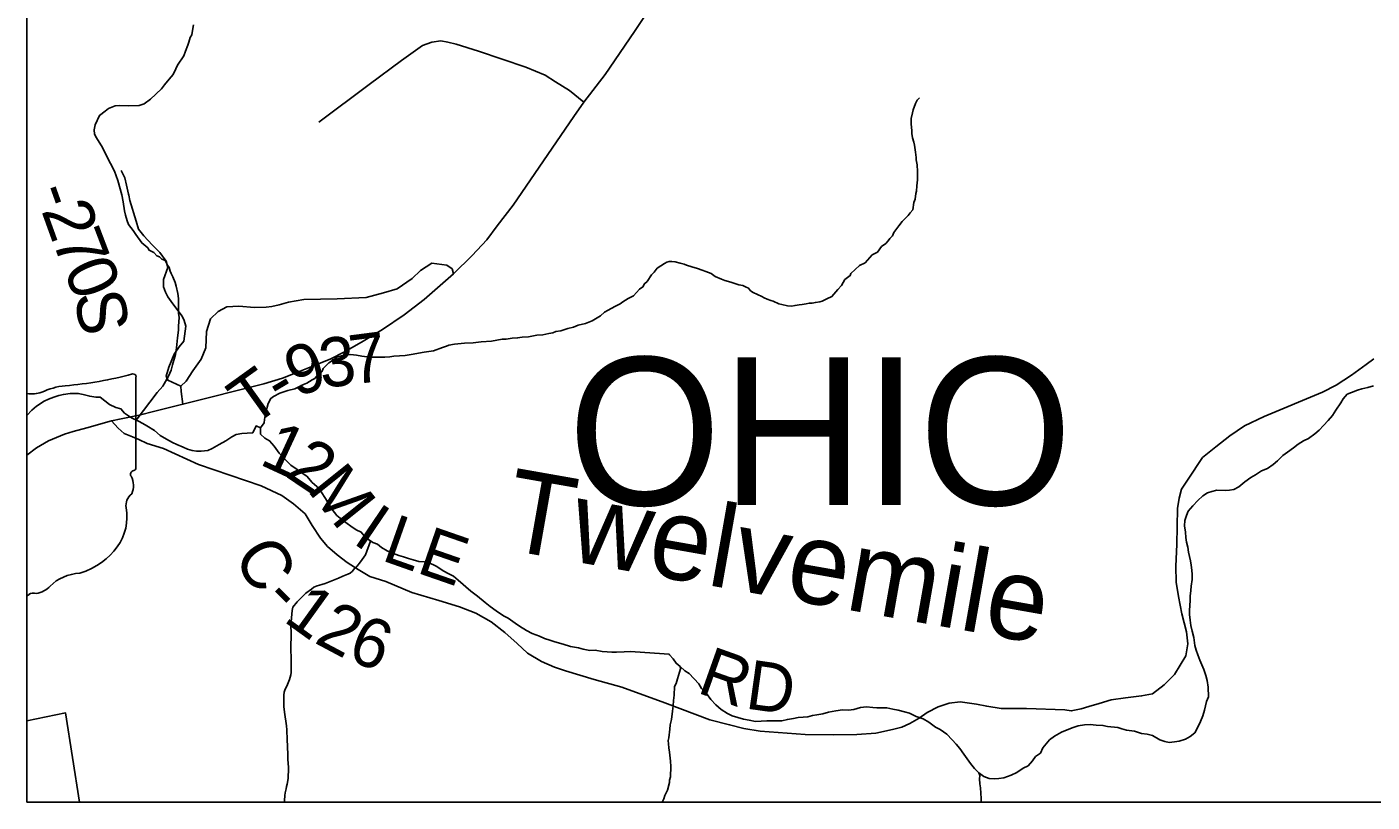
# Model space of a CAD drawing. Extents: x 0 to 39.3, y -3.9 to 22.
# Drawn here: x 1.9 to 3.453, y 13.9 to 14.794 of the extents above; entities that cross this region are included whole.
import ezdxf

# ---------------------------------------------------------------- set-up
doc = ezdxf.new("R2010")
doc.units = 0
for name, color, linetype in [('GM_X_Corporation', 7, 'Continuous'), ('GM_X_Corporation_Text', 7, 'Continuous'), ('GM_X_County_Road', 7, 'Continuous'), ('GM_X_County_Road_Text', 7, 'Continuous'), ('GM_X_Minor_River', 7, 'Continuous'), ('GM_X_Minor_River_Text', 7, 'Continuous'), ('GM_X_State_Route', 7, 'Continuous'), ('GM_X_Township_Road', 7, 'Continuous'), ('GM_X_Township_Road_Text', 7, 'Continuous'), ('GM_X_Township_Text', 7, 'Continuous'), ('SH_Data', 7, 'Continuous')]:
    doc.layers.add(name, color=color, linetype=linetype)

msp = doc.modelspace()

# ---------------------------------------------------------------- linework, layer by layer
at = {"layer": 'GM_X_Corporation'}
msp.add_lwpolyline([(3.5402, 15.8703), (2.8431, 15.7483), (2.8288, 15.7458), (2.6537, 15.7535), (2.5893, 15.7591), (2.5183, 15.7585), (2.4514, 15.75), (2.406, 15.7581), (2.3534, 15.7684), (2.3314, 15.7727), (2.2384, 15.7885), (2.1447, 15.8042), (2.054, 15.8197), (1.9627, 15.8365), (1.9, 15.8496), (1.9, 13.9), (3.8692, 13.9)], dxfattribs=at)
msp.add_lwpolyline([(1.9, 13.9939), (1.9, 13.9), (1.9608, 13.9), (1.9446, 14.0029)], close=True, dxfattribs=at)
at = {"layer": 'GM_X_Corporation_Text'}
msp.add_line((1.9, 14.3714), (1.9, 14.1378), dxfattribs=at)
msp.add_lwpolyline([(2.0259, 14.2859), (2.0259, 14.2859), (2.0259, 14.2859), (2.0259, 14.3907)], dxfattribs=at)
for centre, major_axis, start_param, end_param in [((1.9531, 14.3245), (0.0703, 0), 1.699012, 2.107814), ((1.9085, 14.6584), (0.3495, 0), 4.814394, 5.042369), ((2.0223, 14.391), (0.00367, 0), 6.197627, 7.989034), ((1.9059, 14.3922), (0.0267, 0), 4.489338, 5.145723), ((2.022, 14.2855), (0.00393, 0), 5.054544, 6.418171), ((2.0251, 14.2782), (0.00568, 0), 1.883976, 3.671073), ((1.989, 14.265), (0.0341, 0), 5.934695, 6.695948), ((2.0391, 14.2421), (0.0248, 0), 2.387724, 3.262537), ((1.9281, 14.2287), (0.0874, 0), 5.101753, 6.440018), ((1.965, 14.1259), (0.0479, 0), 1.647645, 2.488434), ((1.9043, 14.1626), (0.0282, 0), 4.937069, 5.64225), ((1.8834, 14.1545), (0.0267, 0), 5.385567, 5.507374), ((1.9075, 14.1351), (0.00752, 0), 1.147584, 2.315152)]:
    msp.add_ellipse(centre, major_axis=major_axis, ratio=0.8, start_param=start_param, end_param=end_param, dxfattribs=at)
at = {"layer": 'GM_X_County_Road'}
for points in [[(2.2941, 14.1614), (2.2959, 14.1603), (2.3142, 14.1544), (2.3442, 14.1417), (2.3755, 14.1325), (2.3993, 14.1251), (2.4183, 14.118), (2.436, 14.1081), (2.4516, 14.0958), (2.4659, 14.083), (2.4778, 14.0718), (2.4939, 14.0622), (2.5089, 14.0557), (2.5217, 14.0513), (2.5548, 14.0414), (2.5868, 14.0327), (2.6365, 14.0145), (2.6884, 13.9948), (2.7111, 13.9893), (2.7276, 13.9848), (2.7466, 13.9817), (2.7984, 13.9781), (2.8306, 13.9776), (2.8581, 13.9778), (2.8798, 13.9796), (2.8991, 13.9836), (2.9098, 13.9864), (2.919, 13.9906), (2.93, 13.9968), (2.9391, 14.0033), (2.9519, 14.0097), (2.9646, 14.0141), (2.9774, 14.0155), (2.996, 14.013), (3.0079, 14.0105), (3.0247, 14.0078), (3.0537, 14.0078), (3.098, 14.0063), (3.1054, 14.0052), (3.1171, 14.0074), (3.1258, 14.0103), (3.1377, 14.0139), (3.1515, 14.0179), (3.1683, 14.0202), (3.1867, 14.0224), (3.1992, 14.0249), (3.2127, 14.0352), (3.2248, 14.0472), (3.2379, 14.0687), (3.2402, 14.0826), (3.2384, 14.0965), (3.2333, 14.1171), (3.2292, 14.137), (3.2267, 14.1538), (3.2261, 14.1721), (3.2274, 14.197), (3.2281, 14.2388), (3.2299, 14.2507), (3.2326, 14.2609), (3.2404, 14.2726), (3.257, 14.2975), (3.2724, 14.3099), (3.2884, 14.3225), (3.3055, 14.3341), (3.3281, 14.3447), (3.3956, 14.373), (3.4113, 14.3809), (3.4291, 14.3926), (3.4461, 14.4047), (3.4546, 14.4114)], [(1.9978, 14.3397), (2.0053, 14.3312), (2.0122, 14.3253), (2.022, 14.3212), (2.0293, 14.3184), (2.0388, 14.3137), (2.0577, 14.308), (2.0979, 14.2896), (2.1705, 14.2648), (2.1944, 14.2538), (2.2079, 14.244), (2.2211, 14.2326), (2.2294, 14.2189), (2.2388, 14.2046), (2.2471, 14.195), (2.2583, 14.1851), (2.2697, 14.1764), (2.2824, 14.1683), (2.2941, 14.1614)]]:
    msp.add_lwpolyline(points, dxfattribs=at)
at = {"layer": 'GM_X_Minor_River'}
for points in [[(2.0263, 14.3405), (2.0504, 14.3724), (2.057, 14.3799), (2.0586, 14.3825), (2.0633, 14.3912), (2.0665, 14.3984), (2.0681, 14.4044), (2.0714, 14.4162), (2.0726, 14.4241), (2.074, 14.4355), (2.0749, 14.4443), (2.075, 14.4492), (2.0756, 14.4591), (2.0749, 14.4641), (2.0751, 14.4736), (2.0748, 14.4808), (2.0742, 14.4869), (2.0724, 14.4953), (2.0713, 14.4995), (2.0684, 14.5061), (2.0666, 14.5099), (2.0655, 14.5126), (2.0644, 14.5168), (2.0622, 14.5195), (2.0596, 14.5249), (2.0558, 14.5264), (2.0532, 14.5291), (2.0498, 14.5303), (2.0465, 14.5342), (2.0412, 14.5366), (2.0397, 14.5393), (2.0326, 14.5451), (2.0259, 14.5547), (2.0226, 14.5594), (2.0174, 14.5663), (2.0159, 14.5705), (2.0137, 14.577), (2.0127, 14.582), (2.011, 14.5923), (2.0096, 14.6007), (2.005, 14.6171), (2.001, 14.6279), (1.9918, 14.6455), (1.9874, 14.6551), (1.9803, 14.6663), (1.9781, 14.6705), (1.9778, 14.6755), (1.9787, 14.6812), (1.9839, 14.6921), (1.9904, 14.697), (1.9943, 14.7003), (2.0019, 14.7032), (2.0073, 14.7035), (2.0176, 14.7033), (2.0297, 14.7035), (2.0355, 14.7057), (2.0428, 14.7109), (2.0552, 14.7229), (2.0587, 14.7274), (2.0642, 14.7338), (2.0688, 14.7394), (2.072, 14.7458), (2.074, 14.75), (2.081, 14.7609), (2.083, 14.7662), (2.0858, 14.7734), (2.087, 14.7768), (2.0886, 14.7821), (2.0902, 14.7851), (2.0911, 14.79), (2.0923, 14.7968)], [(2.7384, 14.4879), (2.7482, 14.4831), (2.7512, 14.4816), (2.7546, 14.48), (2.7588, 14.4788), (2.7614, 14.478), (2.7679, 14.4748), (2.7716, 14.474), (2.7781, 14.4724), (2.7826, 14.4723), (2.7868, 14.473), (2.7914, 14.4736), (2.7949, 14.474), (2.7994, 14.4747), (2.8029, 14.4754), (2.8063, 14.4757), (2.8101, 14.4764), (2.8151, 14.477), (2.8178, 14.4778), (2.8235, 14.4807), (2.8293, 14.4833), (2.8359, 14.4915), (2.8402, 14.496), (2.8441, 14.5028), (2.8503, 14.5073), (2.8511, 14.5099), (2.8611, 14.5189), (2.8677, 14.5222), (2.8758, 14.5312), (2.882, 14.5345), (2.8863, 14.5409), (2.8913, 14.5443), (2.894, 14.5476), (2.896, 14.5503), (2.8991, 14.5533), (2.9007, 14.557), (2.9065, 14.5646), (2.9104, 14.5698), (2.9174, 14.5769), (2.9197, 14.5799), (2.9225, 14.5833), (2.9237, 14.5917), (2.9253, 14.5954), (2.9262, 14.6019), (2.927, 14.6049), (2.9271, 14.611), (2.9276, 14.6144), (2.928, 14.6179), (2.9282, 14.6274), (2.9276, 14.635), (2.9265, 14.6411), (2.9266, 14.6438), (2.9259, 14.6499), (2.9252, 14.6525), (2.9246, 14.6579), (2.9239, 14.6613), (2.9224, 14.6663), (2.9214, 14.6713), (2.9214, 14.6743), (2.9208, 14.6823), (2.9209, 14.6861), (2.9209, 14.6888), (2.9222, 14.6952), (2.923, 14.6986), (2.9258, 14.7058), (2.9278, 14.7096), (2.9305, 14.7126)], [(2.1695, 14.3319), (2.1738, 14.3377), (2.1743, 14.3415), (2.1751, 14.346), (2.1767, 14.3521), (2.1772, 14.3555), (2.1784, 14.3597), (2.1816, 14.3657), (2.1846, 14.368), (2.1919, 14.3716), (2.1965, 14.3731), (2.2011, 14.3749), (2.2092, 14.3767), (2.2192, 14.3818), (2.223, 14.3833), (2.2291, 14.387), (2.2322, 14.3888), (2.2353, 14.3926), (2.2407, 14.3971), (2.2419, 14.4001), (2.2485, 14.4068), (2.2539, 14.4102), (2.2578, 14.4131), (2.2631, 14.415), (2.2662, 14.4157), (2.2735, 14.4163), (2.2803, 14.4154), (2.2867, 14.4146), (2.2959, 14.4133), (2.3061, 14.4131), (2.313, 14.4133), (2.3191, 14.4136), (2.3237, 14.4143), (2.3366, 14.4152), (2.3435, 14.4162), (2.3584, 14.419), (2.3695, 14.4207), (2.3798, 14.4244), (2.3844, 14.4258), (2.3871, 14.4273), (2.3936, 14.4283), (2.405, 14.4293), (2.4153, 14.4299), (2.4245, 14.4308), (2.4363, 14.4318), (2.4485, 14.4339), (2.4531, 14.4342), (2.4603, 14.4352), (2.4664, 14.4354), (2.4718, 14.4365), (2.479, 14.4368), (2.4885, 14.4385), (2.4954, 14.4391), (2.5023, 14.4405), (2.5069, 14.4412), (2.5107, 14.4427), (2.5164, 14.4437), (2.5245, 14.4463), (2.531, 14.448), (2.5363, 14.4502), (2.5447, 14.452), (2.5524, 14.4553), (2.562, 14.4608), (2.5667, 14.4653), (2.5709, 14.4675), (2.5786, 14.4716), (2.5848, 14.4749), (2.5878, 14.4771), (2.594, 14.4808), (2.6001, 14.4842), (2.6071, 14.4917), (2.611, 14.4943), (2.613, 14.498), (2.6161, 14.5006), (2.6208, 14.5082), (2.6242, 14.5115), (2.6277, 14.516), (2.6358, 14.5212), (2.6385, 14.5227), (2.6412, 14.5238), (2.6443, 14.5238), (2.6484, 14.5233), (2.6541, 14.5217), (2.6587, 14.5205), (2.6613, 14.5193), (2.6677, 14.5173), (2.6742, 14.5156), (2.6795, 14.5136), (2.6836, 14.512), (2.6897, 14.5097), (2.6946, 14.5065), (2.7017, 14.5034), (2.7055, 14.5018), (2.7127, 14.4997), (2.7161, 14.4985), (2.7218, 14.4969), (2.7264, 14.4961), (2.7294, 14.4945), (2.7328, 14.4929), (2.7354, 14.4898), (2.7384, 14.4879)], [(3.2604, 14.0111), (3.2616, 14.016), (3.264, 14.0213), (3.2634, 14.0327), (3.2624, 14.0403), (3.261, 14.046), (3.2584, 14.0529), (3.2541, 14.0636), (3.2515, 14.0698), (3.2497, 14.0751), (3.2483, 14.0808), (3.2469, 14.09), (3.2451, 14.0972), (3.2437, 14.1037), (3.2427, 14.1098), (3.2421, 14.1163), (3.2418, 14.1212), (3.2427, 14.1326), (3.2428, 14.1376), (3.2437, 14.144), (3.2441, 14.1489), (3.245, 14.1569), (3.2451, 14.1626), (3.2448, 14.1675), (3.2438, 14.1733), (3.2431, 14.1782), (3.242, 14.1832), (3.241, 14.1885), (3.2399, 14.1939), (3.2385, 14.2), (3.2379, 14.2053), (3.2372, 14.2114), (3.2362, 14.2186), (3.2367, 14.2247), (3.2387, 14.2307), (3.2406, 14.2356), (3.2457, 14.2416), (3.2515, 14.248), (3.2572, 14.2532), (3.2626, 14.2566), (3.2676, 14.2584), (3.2736, 14.2598), (3.2831, 14.2596), (3.2881, 14.2599), (3.293, 14.2606), (3.2991, 14.2635), (3.3057, 14.2695), (3.3126, 14.2743), (3.3183, 14.2777), (3.3252, 14.2821), (3.3321, 14.285), (3.3386, 14.2895), (3.3436, 14.2936), (3.3498, 14.2999), (3.3551, 14.3036), (3.362, 14.3085), (3.3674, 14.3129), (3.3735, 14.3166), (3.3793, 14.3196), (3.3866, 14.3248), (3.3916, 14.3289), (3.3966, 14.3345), (3.402, 14.3401), (3.407, 14.3461), (3.4109, 14.3521), (3.4167, 14.3604), (3.4195, 14.3652), (3.4241, 14.3705), (3.4291, 14.3727), (3.4359, 14.3752), (3.4409, 14.3767), (3.4477, 14.3784), (3.4542, 14.3802)], [(1.9, 14.3461), (1.9057, 14.352), (1.9111, 14.3568), (1.92, 14.3627), (1.925, 14.3649), (1.9311, 14.3671), (1.9368, 14.3689), (1.9422, 14.3703), (1.9498, 14.3713), (1.9593, 14.3715), (1.9649, 14.3702), (1.9725, 14.3682), (1.9797, 14.3673), (1.9846, 14.3672), (1.9954, 14.3586), (2.0026, 14.3554), (2.0086, 14.3537), (2.0127, 14.3487), (2.0209, 14.3432), (2.0288, 14.3393), (2.0337, 14.3369), (2.0386, 14.3341), (2.0472, 14.3286), (2.0539, 14.3228), (2.0611, 14.3185), (2.0682, 14.3149), (2.0731, 14.3125), (2.0802, 14.3094), (2.0855, 14.3073), (2.0908, 14.3057), (2.0957, 14.3049), (2.101, 14.3048), (2.109, 14.3057), (2.114, 14.3079), (2.1221, 14.3127), (2.1297, 14.3167), (2.1367, 14.3212), (2.1417, 14.3241), (2.1481, 14.3251), (2.1542, 14.3257), (2.1607, 14.326), (2.1646, 14.3339), (2.1695, 14.3319), (2.1698, 14.3243), (2.1746, 14.32), (2.1802, 14.3169), (2.1854, 14.3107), (2.191, 14.3026), (2.1984, 14.2948), (2.2047, 14.2886), (2.2118, 14.2835), (2.2178, 14.2796), (2.2231, 14.2761), (2.2294, 14.2687), (2.2346, 14.2641), (2.2398, 14.2579), (2.2445, 14.2502), (2.2482, 14.2444), (2.2523, 14.2375), (2.2578, 14.2305), (2.2653, 14.2243), (2.2739, 14.2184), (2.2802, 14.2141), (2.2859, 14.2113), (2.2907, 14.2052), (2.2993, 14.1993), (2.3046, 14.1977), (2.3094, 14.1938), (2.3158, 14.1898), (2.3233, 14.1866), (2.3294, 14.1846), (2.3347, 14.183), (2.3403, 14.181), (2.346, 14.1793), (2.3524, 14.1777), (2.3584, 14.1772), (2.3634, 14.1763), (2.3724, 14.172), (2.3814, 14.1665), (2.3863, 14.1637), (2.3923, 14.1605), (2.3979, 14.1559), (2.4124, 14.1434), (2.4203, 14.1376), (2.4289, 14.1302), (2.4348, 14.1255), (2.4416, 14.1208), (2.4502, 14.1149)], [(2.2966, 14.2011), (2.2908, 14.1853), (2.2888, 14.1827), (2.2849, 14.177), (2.281, 14.1718), (2.2779, 14.1691), (2.276, 14.1665), (2.2733, 14.1639), (2.2706, 14.1628), (2.2648, 14.1606), (2.2598, 14.1584), (2.2518, 14.1551), (2.2441, 14.1522), (2.2403, 14.1511), (2.2349, 14.1493), (2.2311, 14.1479), (2.2284, 14.1456), (2.2218, 14.1412), (2.2145, 14.1337), (2.2121, 14.1311), (2.2071, 14.1247), (2.2063, 14.1209), (2.2053, 14.1125), (2.2048, 14.103), (2.205, 14.0958), (2.2047, 14.076), (2.2049, 14.0661), (2.2051, 14.0577), (2.205, 14.0494), (2.2045, 14.0467), (2.2033, 14.0414), (2.2001, 14.0338), (2.1981, 14.0301), (2.1969, 14.0267), (2.1965, 14.0232), (2.1964, 14.0206), (2.1966, 14.0103), (2.1973, 14.0038), (2.1997, 13.9878), (2.2, 13.9832), (2.2005, 13.9718), (2.2008, 13.9645), (2.2013, 13.9543), (2.2012, 13.9482), (2.2016, 13.9455), (2.2018, 13.939), (2.2016, 13.9272), (2.2004, 13.9208), (2.1995, 13.9181), (2.1991, 13.9151), (2.1983, 13.9105), (2.1978, 13.9075), (2.1973, 13.9018), (2.1972, 13.9)], [(2.4502, 14.1149), (2.4554, 14.1121), (2.4637, 14.1063), (2.4685, 14.1028), (2.4768, 14.098), (2.4832, 14.0945), (2.4918, 14.0913), (2.4975, 14.0889), (2.5035, 14.0869), (2.5092, 14.0848), (2.519, 14.082), (2.5273, 14.0795), (2.5367, 14.0778), (2.542, 14.0766), (2.5496, 14.0749), (2.556, 14.0752), (2.564, 14.0739), (2.5697, 14.0734), (2.575, 14.0729), (2.5807, 14.0728), (2.5894, 14.0733), (2.5962, 14.0736), (2.6023, 14.0735), (2.6412, 14.0706), (2.6419, 14.0698)], [(2.6419, 14.0698), (2.646, 14.0652), (2.6493, 14.0602), (2.6542, 14.0563), (2.6594, 14.0513), (2.6643, 14.0482), (2.6755, 14.0366), (2.6788, 14.0312), (2.6844, 14.0254), (2.6896, 14.0185), (2.6952, 14.0123), (2.7015, 14.0069), (2.7086, 14.0022), (2.7139, 13.9994), (2.7271, 13.9958), (2.7339, 13.9945), (2.7411, 13.9929), (2.7475, 13.9932), (2.754, 13.9938), (2.7661, 13.9936), (2.7714, 13.9939), (2.7779, 13.9953), (2.7847, 13.9963), (2.7901, 13.9974), (2.7961, 13.9981), (2.8015, 13.9983), (2.8068, 13.9998), (2.8117, 14.0005), (2.8186, 14.0019), (2.8254, 14.0036), (2.8338, 14.0054), (2.8414, 14.0064), (2.8482, 14.0059), (2.8547, 14.0069), (2.8623, 14.0091), (2.8691, 14.0097), (2.8763, 14.0092), (2.8812, 14.0088), (2.8926, 14.0086), (2.8994, 14.0073), (2.9058, 14.0061), (2.913, 14.0041), (2.9187, 14.0024), (2.9266, 13.9989), (2.9345, 13.9961), (2.9412, 13.9922), (2.9487, 13.9863), (2.954, 13.9836), (2.9619, 13.9785), (2.9682, 13.972), (2.9727, 13.9669), (2.9767, 13.9619), (2.9816, 13.9554), (2.9853, 13.95), (2.9893, 13.9446), (2.9938, 13.9388), (2.999, 13.9338), (3.0046, 13.9295), (3.0107, 13.9272), (3.0167, 13.9267), (3.022, 13.9273), (3.0277, 13.928), (3.0361, 13.9309), (3.0426, 13.9342), (3.0499, 13.939), (3.0556, 13.942), (3.0607, 13.9476), (3.0642, 13.9525), (3.0699, 13.9566), (3.0727, 13.9626), (3.0804, 13.972), (3.0862, 13.976), (3.0942, 13.9805), (3.1064, 13.9856), (3.1133, 13.9881), (3.1209, 13.9891), (3.1273, 13.9894), (3.1341, 13.9889), (3.1421, 13.9884), (3.1474, 13.9872), (3.1591, 13.9862), (3.164, 13.9846), (3.1693, 13.983), (3.1784, 13.9817), (3.1867, 13.9793), (3.1931, 13.9784), (3.1991, 13.9768), (3.2078, 13.9717), (3.2134, 13.9697), (3.2187, 13.9689), (3.2248, 13.9695), (3.2301, 13.9702), (3.2374, 13.9727), (3.2427, 13.9757), (3.2481, 13.9798), (3.2508, 13.985), (3.2548, 13.9929), (3.2575, 13.9994), (3.2592, 14.0062), (3.2604, 14.0111)], [(2.6542, 14.0563), (2.6544, 14.0539), (2.6511, 14.0421), (2.6495, 14.0368), (2.6476, 14.0334), (2.647, 14.0235), (2.6465, 14.0171), (2.646, 14.011), (2.6451, 14.0049), (2.6442, 13.9954), (2.6426, 13.989), (2.6421, 13.984), (2.6408, 13.9742), (2.6404, 13.9711), (2.6407, 13.9673), (2.641, 13.9627), (2.6416, 13.9574), (2.643, 13.9471), (2.6432, 13.941), (2.643, 13.9292), (2.6418, 13.9251), (2.6418, 13.9224), (2.6393, 13.9137), (2.6362, 13.9076), (2.6353, 13.9038), (2.6331, 13.9)], [(2.999, 13.9338), (2.9998, 13.9307), (2.9997, 13.9269), (2.9999, 13.9212), (3.0006, 13.9166), (3.0013, 13.9101), (3.0015, 13.904), (3.0017, 13.9)]]:
    msp.add_lwpolyline(points, dxfattribs=at)
at = {"layer": 'GM_X_State_Route'}
for points in [[(2.5315, 14.691), (2.5428, 14.7075), (2.5675, 14.7392), (2.6014, 14.7891), (2.6233, 14.8215)], [(1.9, 14.3001), (1.9111, 14.3086), (1.9249, 14.3166), (1.9434, 14.3245), (1.9533, 14.3277), (1.9692, 14.3318), (1.9978, 14.3397), (2.009, 14.3423), (2.0295, 14.3462), (2.0477, 14.3511), (2.0801, 14.359), (2.1733, 14.3827), (2.1951, 14.389), (2.2134, 14.3962), (2.2386, 14.4065), (2.2508, 14.4115), (2.2667, 14.4196), (2.2861, 14.4306), (2.3104, 14.4452), (2.3354, 14.462), (2.3585, 14.4797), (2.3926, 14.5093), (2.4139, 14.5307), (2.431, 14.5485), (2.443, 14.5647), (2.4614, 14.5887), (2.5315, 14.691)]]:
    msp.add_lwpolyline(points, dxfattribs=at)
at = {"layer": 'GM_X_Township_Road'}
for points in [[(2.5428, 14.7075), (2.5262, 14.7209), (2.5103, 14.7311), (2.4983, 14.7385), (2.476, 14.7479), (2.4212, 14.7663), (2.3956, 14.7744), (2.3857, 14.7768), (2.3777, 14.7784), (2.3673, 14.7768), (2.3565, 14.7728), (2.3323, 14.7556), (2.2951, 14.7277), (2.2369, 14.6843)], [(2.0173, 14.6012), (2.0151, 14.6118), (2.0129, 14.6201), (2.009, 14.6285)], [(2.0777, 14.3797), (2.0626, 14.3869), (2.0607, 14.3914), (2.064, 14.4019), (2.0701, 14.4167), (2.0759, 14.4252), (2.0812, 14.4318), (2.0835, 14.4492), (2.0814, 14.4554), (2.0791, 14.4606), (2.0685, 14.4747), (2.0626, 14.4828), (2.0599, 14.4881), (2.0578, 14.4945), (2.0578, 14.5027), (2.0625, 14.5166), (2.0609, 14.524), (2.0536, 14.5341), (2.0446, 14.5429), (2.0351, 14.5531), (2.029, 14.5611), (2.026, 14.57), (2.0188, 14.5941), (2.0175, 14.6002), (2.0173, 14.6012)], [(2.0801, 14.359), (2.0779, 14.3736), (2.0777, 14.3797), (2.084, 14.3857), (2.0915, 14.3974), (2.1011, 14.411), (2.1067, 14.424), (2.1073, 14.4429), (2.1119, 14.4575), (2.1206, 14.4658), (2.1307, 14.4715), (2.1445, 14.4723), (2.1628, 14.4707), (2.1761, 14.4711), (2.1827, 14.4717), (2.1911, 14.4738), (2.2021, 14.4769), (2.2195, 14.4797), (2.2581, 14.4806), (2.2915, 14.482), (2.3118, 14.4874), (2.3275, 14.4921), (2.3446, 14.504), (2.3545, 14.5134), (2.3673, 14.5219), (2.3848, 14.5193), (2.391, 14.515), (2.3926, 14.5093)]]:
    msp.add_lwpolyline(points, dxfattribs=at)
at = {"layer": 'SH_Data'}
msp.add_lwpolyline([(1.9, 21.1), (9.1, 21.1), (9.1, 13.9), (1.9, 13.9)], close=True, dxfattribs=at)

# ---------------------------------------------------------------- texts
at = {"layer": 'GM_X_County_Road_Text'}
for s, rotation, p in [('1', 335.1318, (2.1669, 14.2903)), ('2', 326.2529, (2.1967, 14.2767)), ('M', 308.6598, (2.2224, 14.2604)), ('I', 325.8457, (2.2745, 14.1997)), ('L', 340.5481, (2.3079, 14.1794)), ('E', 340.8601, (2.3483, 14.1652)), ('C', 301.4758, (2.1371, 14.1836)), ('-', 315.4322, (2.1708, 14.132)), ('1', 324.2384, (2.1947, 14.1095)), ('2', 331.9823, (2.2302, 14.0846)), ('6', 338.9263, (2.268, 14.065)), ('R', 340.4307, (2.672, 14.0268)), ('D', 352.0154, (2.728, 14.0082))]:
    msp.add_text(s, height=0.0568, rotation=rotation, dxfattribs=at).set_placement(p)
at = {"layer": 'GM_X_Minor_River_Text'}
msp.add_text('Twelvemile', height=0.0947, rotation=349.9999, dxfattribs=at).set_placement((2.4473, 14.1923))
at = {"layer": 'GM_X_Township_Road_Text'}
for s, rotation, p in [('-', 289.5866, (1.9084, 14.605)), ('2', 289.925, (1.9163, 14.5826)), ('7', 290.8755, (1.9286, 14.5488)), ('0', 292.2144, (1.9416, 14.5147)), ('S', 280.8408, (1.954, 14.4852)), ('7', 7.4108, (2.276, 14.3816)), ('9', 19.6692, (2.2105, 14.3666)), ('3', 6.333, (2.2401, 14.3776)), ('T', 35.7016, (2.1597, 14.3318)), ('-', 30.7509, (2.1931, 14.3559))]:
    msp.add_text(s, height=0.0568, rotation=rotation, dxfattribs=at).set_placement(p)
at = {"layer": 'GM_X_Township_Text'}
msp.add_text('OHIO', height=0.17045, rotation=0, dxfattribs=at).set_placement((2.5243, 14.2426))

doc.saveas('drawing.dxf')
